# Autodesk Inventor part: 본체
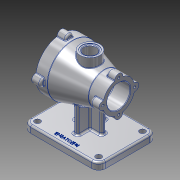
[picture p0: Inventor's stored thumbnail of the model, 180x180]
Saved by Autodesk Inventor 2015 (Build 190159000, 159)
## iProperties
Created: 2020-12
Part Number: 본체
Material: 알루미늄 6061
Document SubType Name: Modeling
Designer: Administrator
Density: 2.7 g/cm^3
Appearance: 알루미늄 - 평지
Mass: 1057.78 g
Surface Area: 850.828 cm^2
Volume: 391.769 cm^3
Author: Administrator
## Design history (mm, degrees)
sketch "스케치1"
  geometry: L1 (-65, 50)-(65, 50); L2 (65, 50)-(65, -50); L3 (65, -50)-(-65, -50); L4 (-65, -50)-(-65, 50); 3 further points
  constraints: 8 end point, 2 midpoint, 2 parallel, 1 horizontal, 1 horizontal alignment, 1 perpendicular, 1 vertical alignment
  dimensions: "d0" = 130 distance of L2.end L3.end; "d1" = 100 distance of L1.end L2.end
extrude "돌출1" new body sketch "스케치1" distance "d2" = 12; taper "d3" = 0 deg
sketch "스케치3"
  geometry: L1 (-65, 0)-(65, 0) reference; L2 (0, 0)-(0, 82); L3 (50, 82)-(-50, 82); L4 (50, 82)-(50, 126); L5 (50, 126)-(30, 126); L6 (-50, 82)-(-50, 109.5); L7 (-50, 109.5)-(-25, 109.5); L8 (-25, 109.5)-(30, 126)
  constraints: 14 end point, 3 vertical, 2 perpendicular, 1 horizontal, 1 midpoint
  dimensions: "d24" = 82 distance of L2.end L2.start; "d25" = 100 distance of L3.start L3.end; "d26" = 44 distance of L3.start L4.end; "d27" = 20 distance of L4.end L5.end; "d28" = 27.5 distance of L3.end L6.end; "d29" = 25 distance of L6.end L7.end
revolve "회전2" sketch "스케치3" stored, may be unused: angle "d30" = 90 deg
sketch "스케치4"
  geometry: L1 (50, 38)-(50, 126) reference; L2 (-50, 54.5)-(-50, 109.5) reference; L3 (50, 82)-(-50, 82); L4 (50, 82)-(50, 114); L5 (50, 114)-(27, 114); L6 (27, 114)-(27, 82); L7 (-50, 82)-(-50, 102); L8 (-50, 102)-(-20, 102); L9 (-20, 102)-(-20, 82); L10 (27, 108)-(-20, 108); L11 (-20, 102)-(-20, 108); 1 further point
  constraints: 18 end point, 5 perpendicular, 5 point on line, 2 midpoint, 1 horizontal
  dimensions: "d31" = 32 distance of L3.start L4.end; "d32" = 23 distance of L4.end L5.end; "d33" = 20 distance of L3.end L7.end; "d34" = 30 distance of L7.end L8.end; "d35" = 26 distance between parallel lines of L3 L10; "d36" = 47 distance between parallel lines of L9 L6 (derived)
revolve "회전3" sketch "스케치4" stored, may be unused: angle "d37" = 90 deg
fillet "모깎기1" dims "d38" = 3
chamfer "모따기1" distance "d39" = 1; stored, may be unused: second distance "d40" = 2, angle "d41" = 45 deg
sketch "스케치5"
  geometry: A1 r 7 centre (44, 0) between (43.443, -6.978) and (43.443, 6.978); A2 r 7 centre (0, 44) between (6.978, 43.443) and (-6.978, 43.443); A3 r 7 centre (-44, 0) between (-43.443, 6.978) and (-43.443, -6.978); A4 r 7 centre (0, -44) between (-6.978, -43.443) and (6.978, -43.443); 2 further points
  constraints: 8 point on circle, 4 centre point, 2 horizontal alignment, 2 vertical alignment, 13 other
  dimensions: "d42" = 7 radius of A1; "d43" = 7 radius of A2; "d44" = 7 radius of A3; "d45" = 7 radius of A4
extrude "돌출2" join sketch "스케치5" distance "d46" = 15; taper "d47" = 0 deg
sketch "스케치6"
  geometry: A1 r 7 centre (-27.5, 0) between (-26.609, 6.943) and (-26.609, -6.943); A2 r 7 centre (0, -27.5) between (-6.943, -26.609) and (6.943, -26.609); A3 r 7 centre (0, 27.5) between (6.943, 26.609) and (-6.943, 26.609); A4 r 7 centre (27.5, 0) between (26.609, -6.943) and (26.609, 6.943); 2 further points
  constraints: 8 point on circle, 4 centre point, 2 horizontal alignment, 2 vertical alignment, 13 other
  dimensions: "d48" = 7 radius of A1; "d49" = 7 radius of A2; "d50" = 7 radius of A3; "d51" = 7 radius of A4
extrude "돌출3" join sketch "스케치6" distance "d52" = 15; taper "d53" = 0 deg
sketch "스케치7"
  geometry: A1 r 7 centre (-55, 0) between (-54.109, 6.943) and (-54.109, -6.943) reference; A2 r 7 centre (-27.5, -27.5) between (-34.443, -26.609) and (-20.557, -26.609) reference; A3 r 7 centre (0, 0) between (-0.891, -6.943) and (-0.891, 6.943) reference; A4 r 7 centre (-27.5, 27.5) between (-20.557, 26.609) and (-34.443, 26.609) reference; 5 further points
  constraints: 4 coincident
hole "구멍1" sketch "스케치7" at (-55, 0), (-27.5, -27.5), (0, 0), (-27.5, 27.5) diameter "d54" = 4.134; stored, may be unused: countersink angle "d58" = 90 deg, drill point angle "d60" = 118 deg; dims "d55" = 9, "d56" = 4, "d57" = 2, "d59" = 11
sketch "스케치8"
  geometry: C1 r 33 at (44, 0) reference; A1 r 44 centre (44, 0) between (87.443, 6.978) and (50.978, 43.443) reference; A2 r 7 centre (44, 44) between (50.978, 43.443) and (37.022, 43.443) reference; A3 r 44 centre (44, 0) between (37.022, 43.443) and (0.557, 6.978) reference; A4 r 7 centre (0, 0) between (0.557, 6.978) and (0.557, -6.978) reference; A5 r 44 centre (44, 0) between (0.557, -6.978) and (37.022, -43.443) reference; A6 r 7 centre (44, -44) between (37.022, -43.443) and (50.978, -43.443) reference; A7 r 44 centre (44, 0) between (50.978, -43.443) and (87.443, -6.978) reference; A8 r 7 centre (88, 0) between (87.443, -6.978) and (87.443, 6.978) reference; 5 further points
  constraints: 4 coincident
hole "구멍2" sketch "스케치8" at (88, 0), (44, 44), (44, -44), (0, 0) diameter "d61" = 4.134; stored, may be unused: countersink angle "d65" = 90 deg, drill point angle "d67" = 118 deg; dims "d62" = 9, "d63" = 4, "d64" = 2, "d66" = 11
node "작업 평면1"
sketch "스케치9"
  geometry: C1 r 17 at (0, 0); 1 further point
  constraints: 1 centre point, 1 coincident
  dimensions: "d69" = 17 radius of C1
extrude "돌출4" join sketch "스케치9" stored distance "d70" = 15; taper "d71" = 0 deg
sketch "스케치10"
  geometry: C1 r 14 at (0, 0); 1 further point
  constraints: 1 centre point, 1 coincident
  dimensions: "d72" = 14 radius of C1
extrude "돌출5" cut sketch "스케치10" distance "d73" = 1; taper "d74" = 0 deg
sketch "스케치11"
  geometry: C1 r 11 at (0, 0); 1 further point
  constraints: 1 centre point, 1 coincident
  dimensions: "d75" = 11 radius of C1
extrude "돌출6" cut sketch "스케치11" distance "d76" = 32; taper "d77" = 0 deg
chamfer "모따기2" distance "d78" = 1; stored, may be unused: second distance "d79" = 2, angle "d80" = 45 deg
fillet "모깎기2" dims "d81" = 1
fillet "모깎기3" dims "d82" = 3
fillet "모깎기4" dims "d83" = 1
sketch "스케치12"
  geometry: L1 (65, 0)-(-65, 0) reference; L2 (-65, 12)-(65, 12) reference; L3 (24, 12)-(24, 45.511); L4 (-24, 12)-(-24, 55.931) reference; L5 (24, 12)-(-24, 12); L6 (-24, 55.931)-(24, 45.511) reference; 1 further point
  constraints: 8 end point, 2 point on line, 1 parallel, 1 vertical, 1 other
  dimensions: "d85" = 48 distance between parallel lines of L3 L4
extrude "돌출7" join sketch "스케치12" stored distance "d86" = 8; taper "d87" = 0 deg
sketch "스케치13"
  geometry: L1 (50, 12)-(-50, 12) reference; L2 (-25, 12)-(-25, 65.8); L3 (25, 12)-(25, 65.8) reference; L4 (-25, 12)-(25, 12); C1 r 26 at (0, 82) reference; A1 r 29.79 centre (0, 82) between (-25, 65.8) and (25, 65.8) reference; 1 further point
  constraints: 6 end point, 2 point on circle, 2 point on line, 1 centre point, 1 coincident, 1 parallel, 1 vertical, 1 other
  dimensions: "d89" = 50 distance between parallel lines of L2 L3
extrude "돌출8" join sketch "스케치13" stored distance "d90" = 8; taper "d91" = 0 deg
fillet "모깎기5" dims "d92" = 12
sketch "스케치14"
  geometry: C1 r 5 at (-53, 38); C2 r 5 at (53, 38); C3 r 5 at (-53, -38); C4 r 5 at (53, -38); A1 r 12 centre (-53, 38) between (-53, 50) and (-65, 38) reference; A2 r 12 centre (53, 38) between (65, 38) and (53, 50) reference; A3 r 12 centre (53, -38) between (53, -50) and (65, -38) reference; A4 r 12 centre (-53, -38) between (-65, -38) and (-53, -50) reference; 1 further point
  constraints: 4 centre point, 4 coincident
  dimensions: "d93" = 5 radius of C1; "d94" = 5 radius of C2; "d95" = 5 radius of C3; "d96" = 5 radius of C4
extrude "돌출9" cut sketch "스케치14" stored distance "d97" = 8; taper "d98" = 0 deg
fillet "모깎기6" dims "d99" = 3
fillet "모깎기8" dims "d101" = 3
fillet "모깎기9" dims "d102" = 3
sketch "스케치15"
  geometry: L1 (-53, -50)-(53, -50) reference; 2 further points
  constraints: 1 vertical alignment, 1 other
  dimensions: "d103" = 10 distance from line of L1 point (0, -40)
feature "엠보싱1" sketch "스케치15" dims "d0" = 130, "d1" = 100, "d104" = 0.5, "d105" = 0
fillet "모깎기10" dims "d106" = 3
node "솔리드1"
node "투영된 루프1"
other parameters: "d68" = 127
